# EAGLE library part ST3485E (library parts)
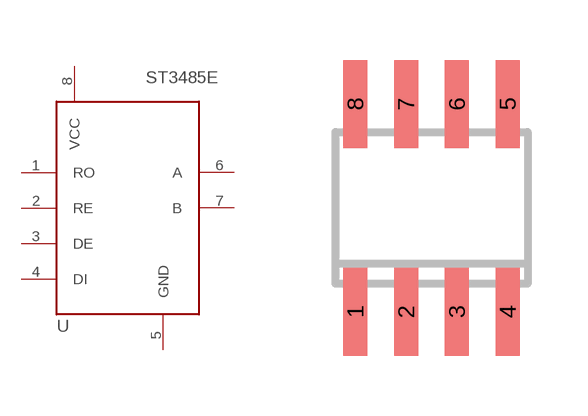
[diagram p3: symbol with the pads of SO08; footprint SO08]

Designator prefix -

## ST3485E  [SO08]
1  RO
2  RE
3  DE
4  DI
5  GND
6  A
7  B
8  VCC

## Footprint SO08 (pad centres in mm)
Small Outline Package 8 NS Package M08A
smd 0.6 x 2.2: 1 -1.905,-2.6; 2 -0.635,-2.6; 3 0.635,-2.6; 4 1.905,-2.6; 5 1.905,2.6; 6 0.635,2.6; 7 -0.635,2.6; 8 -1.905,2.6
